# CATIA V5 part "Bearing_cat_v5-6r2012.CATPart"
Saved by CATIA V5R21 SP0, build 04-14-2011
Part number: Bearing
Bounding box of the stored display mesh (mm): x -10 to 10, y -17.5 to 17.5, z -17.322 to 17.322
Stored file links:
  D:\CATIA V5R21 E-RESOURCES\CATIA-V5R21\catia-v5r21-Tut\c16-catia-v5r21-tut\c16-catia-v5r21-tut03\Bearing_cat_v5r21.CATPart
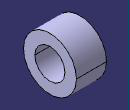
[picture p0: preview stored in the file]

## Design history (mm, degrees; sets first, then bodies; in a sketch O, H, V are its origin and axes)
Body1 (main body)
  Sketch1 on yz-plane, origin (0, 0, 0), H (0, 1, 0), V (0, 0, 1)
    circle A1 centre (0, 0) radius 10
    circle A2 centre (0, 0) radius 17.5
    radius A1 = 10
    radius A2 = 17.5
  Pad1: profile Sketch1, direction (1, 0, 0), length 10, mirrored extent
